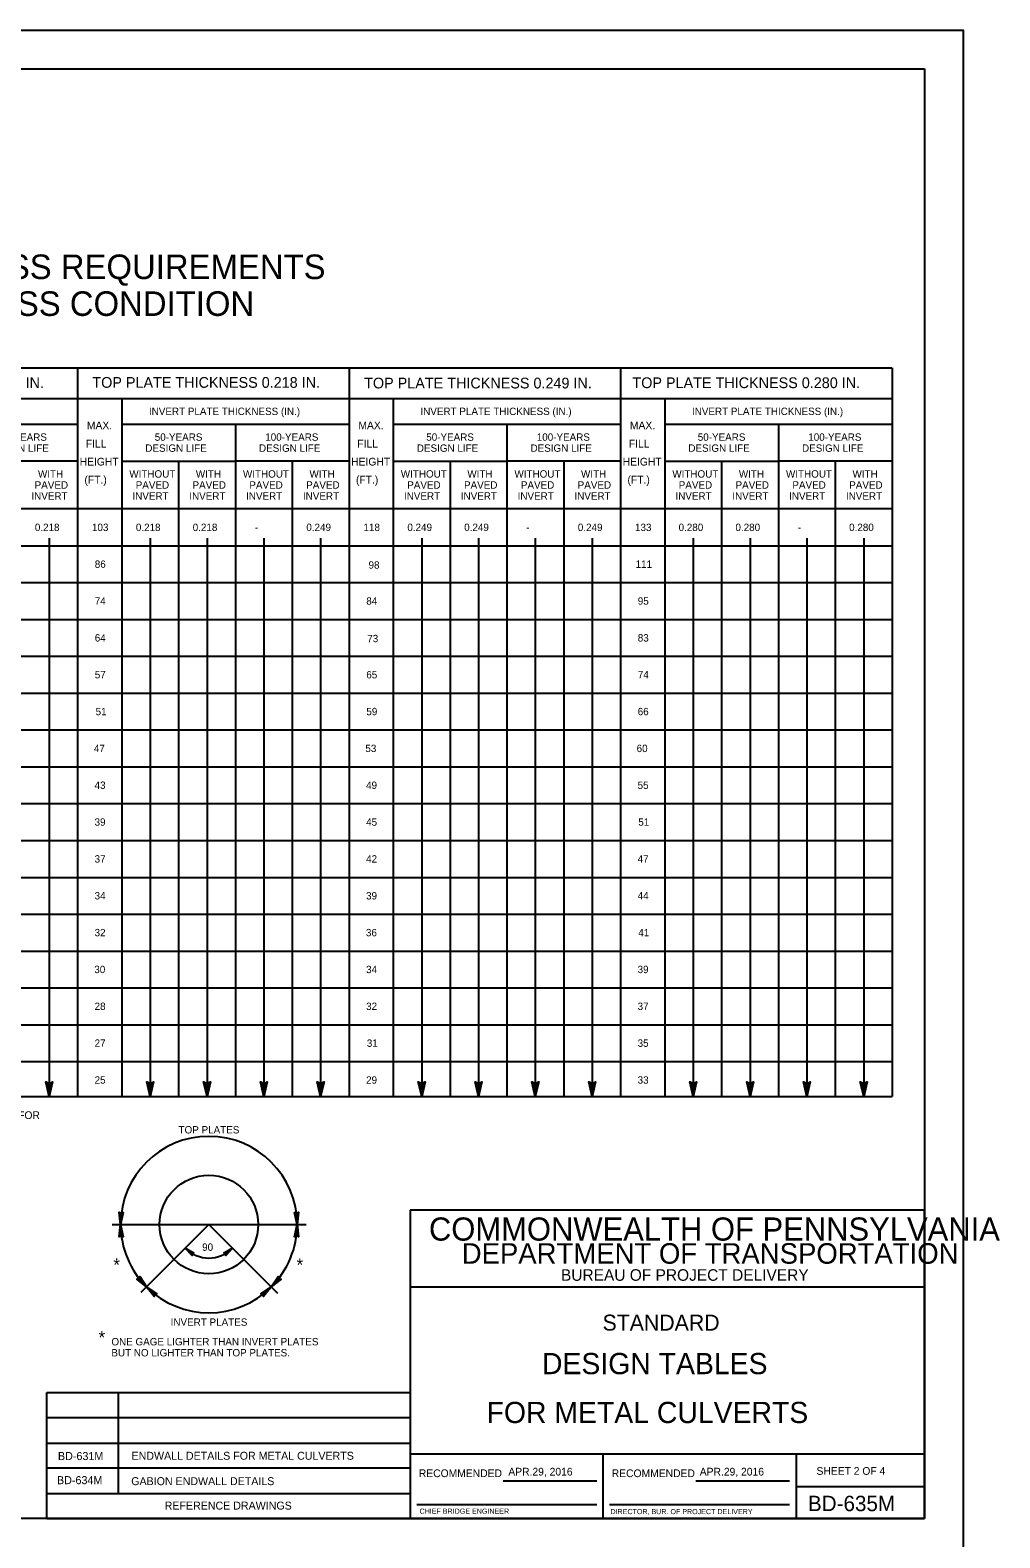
# Model space of a CAD drawing. Extents: x 591 to 2288, y -189 to 2187.
# Drawn here: x 1911 to 2288, y 1601 to 2187 of the extents above; entities that cross this region are included whole.
import ezdxf

# ---------------------------------------------------------------- set-up
doc = ezdxf.new("R2010")
doc.units = 0
for name, color, linetype in [('1', 7, 'Continuous'), ('2', 7, 'Continuous'), ('PLT-BNDY', 7, 'Continuous')]:
    doc.layers.add(name, color=color, linetype=linetype)

msp = doc.modelspace()

# ---------------------------------------------------------------- linework, layer by layer
at = {"layer": '1'}
for p, q in [((1481.73, 2055.84), (2245.62, 2055.84)), ((1928.97, 2055.84), (1928.97, 1772.38)), ((2034.53, 2055.84), (2034.53, 1772.38)), ((2140.11, 2055.84), (2140.11, 1772.38)), ((2245.68, 2055.84), (2245.68, 1772.38)), ((1823.39, 2043.97), (1928.97, 2043.97)), ((1928.97, 2043.97), (2034.53, 2043.97)), ((1946.15, 2043.97), (1946.15, 1772.38)), ((2034.53, 2043.97), (2140.11, 2043.97)), ((2051.72, 2043.97), (2051.72, 1772.38)), ((2140.11, 2043.97), (2245.68, 2043.97)), ((2157.29, 2043.97), (2157.29, 1772.38)), ((1840.58, 2033.93), (1928.97, 2033.93)), ((1946.15, 2033.93), (2034.53, 2033.93)), ((1990.34, 2033.93), (1990.34, 1772.38)), ((2051.72, 2033.93), (2140.11, 2033.93)), ((2095.91, 2033.93), (2095.91, 1772.38)), ((2157.29, 2033.93), (2245.68, 2033.93)), ((2201.48, 2033.93), (2201.48, 1772.38)), ((1928.97, 2019.6), (1884.77, 2019.6)), ((1946.15, 2019.6), (1990.34, 2019.6)), ((1968.25, 2019.6), (1968.25, 1772.38)), ((2034.53, 2019.6), (1990.34, 2019.6)), ((2012.44, 2019.6), (2012.44, 1772.38)), ((2051.72, 2019.6), (2095.91, 2019.6)), ((2073.82, 2019.6), (2073.82, 1772.38)), ((2140.11, 2019.6), (2095.91, 2019.6)), ((2118.01, 2019.6), (2118.01, 1772.38)), ((2157.29, 2019.6), (2201.48, 2019.6)), ((2179.39, 2019.6), (2179.39, 1772.38)), ((2245.68, 2019.6), (2201.48, 2019.6)), ((2223.58, 2019.6), (2223.58, 1772.38)), ((2245.68, 2000.97), (1481.73, 2000.97)), ((1917.92, 1989.55), (1917.92, 1772.38)), ((1957.2, 1989.55), (1957.2, 1772.38)), ((1979.3, 1989.55), (1979.3, 1772.38)), ((2001.39, 1989.55), (2001.39, 1772.38)), ((2023.49, 1989.55), (2023.49, 1772.38)), ((2062.77, 1989.55), (2062.77, 1772.38)), ((2084.87, 1989.55), (2084.87, 1772.38)), ((2106.96, 1989.55), (2106.96, 1772.38)), ((2129.06, 1989.55), (2129.06, 1772.38)), ((2168.34, 1989.55), (2168.34, 1772.38)), ((2190.44, 1989.55), (2190.44, 1772.38)), ((2212.53, 1989.55), (2212.53, 1772.38)), ((2234.63, 1989.55), (2234.63, 1772.38)), ((1481.73, 1986.64), (2245.68, 1986.64)), ((1481.73, 1972.31), (2245.68, 1972.31)), ((1481.73, 1957.97), (2245.68, 1957.97)), ((1481.73, 1943.64), (2245.68, 1943.64)), ((1481.73, 1929.31), (2245.68, 1929.31)), ((1481.73, 1914.98), (2245.68, 1914.98)), ((1481.73, 1900.65), (2245.68, 1900.65)), ((1481.73, 1886.31), (2245.68, 1886.31)), ((1481.73, 1871.98), (2245.68, 1871.98)), ((1481.73, 1857.65), (2245.68, 1857.65)), ((1481.73, 1843.32), (2245.68, 1843.32)), ((1481.73, 1828.99), (2245.68, 1828.99)), ((1481.73, 1814.65), (2245.68, 1814.65)), ((1481.73, 1800.32), (2245.68, 1800.32)), ((1481.73, 1785.99), (2245.68, 1785.99)), ((1481.73, 1772.38), (2245.68, 1772.38)), ((1942.48, 1722.58), (2017.89, 1722.58)), ((1980.03, 1722.58), (1953.62, 1696.17)), ((1980.03, 1722.58), (2006.67, 1695.94)), ((2133.34, 1608.21), (2133.34, 1633.21)), ((2208.34, 1633.21), (2208.34, 1608.21)), ((2094.43, 1622.93), (2130.84, 1622.93)), ((2169.43, 1622.93), (2205.84, 1622.93)), ((2060.84, 1613.71), (2130.84, 1613.71)), ((2135.84, 1613.71), (2205.84, 1613.71))]:
    msp.add_line(p, q, dxfattribs=at)
for points in [[(1918.9, 1777.8), (1918.34, 1777.59), (1917.92, 1772.38), (1918.9, 1777.8), (1919.24, 1778.08), (1917.92, 1772.38), (1917.55, 1777.59), (1916.99, 1777.78), (1917.92, 1772.38), (1916.62, 1778.08), (1916.99, 1777.78)], [(1958.18, 1777.8), (1957.61, 1777.59), (1957.2, 1772.38), (1958.18, 1777.8), (1958.52, 1778.08), (1957.2, 1772.38), (1956.83, 1777.59), (1956.26, 1777.78), (1957.2, 1772.38), (1955.89, 1778.08), (1956.26, 1777.78)], [(1980.28, 1777.8), (1979.71, 1777.59), (1979.3, 1772.38), (1980.28, 1777.8), (1980.62, 1778.08), (1979.3, 1772.38), (1978.92, 1777.59), (1978.37, 1777.78), (1979.3, 1772.38), (1977.99, 1778.08), (1978.37, 1777.78)], [(2002.37, 1777.8), (2001.81, 1777.59), (2001.39, 1772.38), (2002.37, 1777.8), (2002.71, 1778.08), (2001.39, 1772.38), (2001.02, 1777.59), (2000.46, 1777.78), (2001.39, 1772.38), (2000.09, 1778.08), (2000.46, 1777.78)], [(2024.47, 1777.8), (2023.91, 1777.59), (2023.49, 1772.38), (2024.47, 1777.8), (2024.81, 1778.08), (2023.49, 1772.38), (2023.12, 1777.59), (2022.56, 1777.78), (2023.49, 1772.38), (2022.19, 1778.08), (2022.56, 1777.78)], [(2063.75, 1777.8), (2063.18, 1777.59), (2062.77, 1772.38), (2063.75, 1777.8), (2064.09, 1778.08), (2062.77, 1772.38), (2062.4, 1777.59), (2061.84, 1777.78), (2062.77, 1772.38), (2061.46, 1778.08), (2061.84, 1777.78)], [(2085.85, 1777.8), (2085.28, 1777.59), (2084.87, 1772.38), (2085.85, 1777.8), (2086.19, 1778.08), (2084.87, 1772.38), (2084.49, 1777.59), (2083.94, 1777.78), (2084.87, 1772.38), (2083.56, 1778.08), (2083.94, 1777.78)], [(2107.94, 1777.8), (2107.38, 1777.59), (2106.96, 1772.38), (2107.94, 1777.8), (2108.28, 1778.08), (2106.96, 1772.38), (2106.59, 1777.59), (2106.03, 1777.78), (2106.96, 1772.38), (2105.66, 1778.08), (2106.03, 1777.78)], [(2130.04, 1777.8), (2129.48, 1777.59), (2129.06, 1772.38), (2130.04, 1777.8), (2130.39, 1778.08), (2129.06, 1772.38), (2128.69, 1777.59), (2128.13, 1777.78), (2129.06, 1772.38), (2127.76, 1778.08), (2128.13, 1777.78)], [(2169.32, 1777.8), (2168.75, 1777.59), (2168.34, 1772.38), (2169.32, 1777.8), (2169.66, 1778.08), (2168.34, 1772.38), (2167.97, 1777.59), (2167.41, 1777.78), (2168.34, 1772.38), (2167.03, 1778.08), (2167.41, 1777.78)], [(2191.42, 1777.8), (2190.86, 1777.59), (2190.44, 1772.38), (2191.42, 1777.8), (2191.76, 1778.08), (2190.44, 1772.38), (2190.07, 1777.59), (2189.51, 1777.78), (2190.44, 1772.38), (2189.14, 1778.08), (2189.51, 1777.78)], [(2213.51, 1777.8), (2212.95, 1777.59), (2212.53, 1772.38), (2213.51, 1777.8), (2213.86, 1778.08), (2212.53, 1772.38), (2212.16, 1777.59), (2211.6, 1777.78), (2212.53, 1772.38), (2211.23, 1778.08), (2211.6, 1777.78)], [(2235.61, 1777.8), (2235.05, 1777.59), (2234.63, 1772.38), (2235.61, 1777.8), (2235.96, 1778.08), (2234.63, 1772.38), (2234.26, 1777.59), (2233.7, 1777.78), (2234.63, 1772.38), (2233.33, 1778.08), (2233.7, 1777.78)], [(1946.51, 1727.1), (1946.18, 1726.94), (1945.7, 1722.59), (1946.51, 1727.1), (1946.72, 1727.32), (1945.7, 1722.59), (1945.72, 1726.97), (1945.4, 1727.14), (1945.7, 1722.59), (1945.2, 1727.4), (1945.4, 1727.14)], [(2014.68, 1727.16), (2014.36, 1726.97), (2014.35, 1722.59), (2014.68, 1727.16), (2014.87, 1727.4), (2014.35, 1722.59), (2013.9, 1726.94), (2013.57, 1727.08), (2014.35, 1722.59), (2013.34, 1727.32), (2013.57, 1727.08)], [(1945.37, 1718.01), (1945.69, 1718.2), (1945.7, 1722.58), (1945.37, 1718.01), (1945.18, 1717.77), (1945.7, 1722.58), (1946.15, 1718.23), (1946.48, 1718.09), (1945.7, 1722.58), (1946.71, 1717.85), (1946.48, 1718.09)], [(2013.54, 1718.07), (2013.88, 1718.22), (2014.35, 1722.58), (2013.54, 1718.07), (2013.33, 1717.85), (2014.35, 1722.58), (2014.34, 1718.2), (2014.65, 1718.03), (2014.35, 1722.58), (2014.86, 1717.77), (2014.65, 1718.03)], [(1973.44, 1710.84), (1973.48, 1711.13), (1970.82, 1713.37), (1973.44, 1710.84), (1973.49, 1710.59), (1970.82, 1713.37), (1973.71, 1711.42), (1973.96, 1711.55), (1970.82, 1713.37), (1974.22, 1711.57), (1973.96, 1711.55)], [(1986.07, 1711.56), (1986.34, 1711.43), (1989.23, 1713.37), (1986.07, 1711.56), (1985.82, 1711.57), (1989.23, 1713.37), (1986.56, 1711.14), (1986.62, 1710.86), (1989.23, 1713.37), (1986.56, 1710.6), (1986.62, 1710.86)], [(1953.14, 1702.07), (1953.01, 1701.72), (1955.76, 1698.31), (1953.14, 1702.07), (1953.13, 1702.37), (1955.76, 1698.31), (1952.67, 1701.41), (1952.32, 1701.31), (1955.76, 1698.31), (1952, 1701.35), (1952.32, 1701.31)], [(2007.76, 1701.3), (2007.4, 1701.4), (2004.3, 1698.31), (2007.76, 1701.3), (2008.07, 1701.34), (2004.3, 1698.31), (2007.06, 1701.7), (2006.93, 1702.04), (2004.3, 1698.31), (2006.93, 1702.37), (2006.93, 1702.04)], [(1958.75, 1694.84), (1958.85, 1695.2), (1955.76, 1698.31), (1958.75, 1694.84), (1958.79, 1694.54), (1955.76, 1698.31), (1959.15, 1695.54), (1959.49, 1695.68), (1955.76, 1698.31), (1959.82, 1695.67), (1959.49, 1695.68)], [(2000.54, 1695.69), (2000.89, 1695.56), (2004.3, 1698.31), (2000.54, 1695.69), (2000.23, 1695.69), (2004.3, 1698.31), (2001.19, 1695.23), (2001.29, 1694.87), (2004.3, 1698.31), (2001.25, 1694.55), (2001.29, 1694.87)]]:
    msp.add_lwpolyline(points, dxfattribs=at)
msp.add_circle((1980.03, 1722.58), 19.18, dxfattribs=at)
for radius, start, end in [(34.32, 0.01323, 179.98674), (34.32, 180, 225.00216), (34.32, 315, 0), (13.02, 225.00216, 315), (34.32, 225.00216, 315)]:
    msp.add_arc((1980.03, 1722.58), radius, start, end, dxfattribs=at)
at = {"layer": '2'}
for p, q in [((1472.34, 2172.21), (2258.34, 2172.21)), ((2258.34, 2172.21), (2258.34, 1608.21)), ((2258.34, 1728.21), (2058.34, 1728.21)), ((2058.34, 1728.21), (2058.34, 1608.21)), ((2258.34, 1608.21), (2258.34, 1728.21)), ((2258.34, 1698.21), (2058.34, 1698.21)), ((1916.96, 1608.21), (1916.96, 1657.21)), ((1916.96, 1657.21), (2058.34, 1657.21)), ((1916.96, 1657.21), (2058.34, 1657.21)), ((1944.84, 1618.34), (1944.84, 1657.21)), ((1916.96, 1647.59), (2058.34, 1647.59)), ((1916.96, 1637.59), (2058.34, 1637.59)), ((2258.34, 1633.21), (2058.34, 1633.21)), ((1916.96, 1627.96), (2058.34, 1627.96)), ((2208.34, 1620.71), (2258.34, 1620.71)), ((1916.96, 1617.96), (2058.34, 1617.96)), ((2258.34, 1608.21), (1472.34, 1608.21)), ((2258.34, 1608.21), (1472.34, 1608.21)), ((1916.96, 1608.21), (2058.34, 1608.21)), ((2058.34, 1608.21), (2258.34, 1608.21)), ((2058.34, 1608.21), (2258.34, 1608.21))]:
    msp.add_line(p, q, dxfattribs=at)
at = {"layer": 'PLT-BNDY'}
msp.add_lwpolyline([(1432.34, 2187.21), (2273.34, 2187.21), (2273.34, 1593.21), (1432.34, 1593.21)], close=True, dxfattribs=at)

# ---------------------------------------------------------------- texts
at = {"layer": '1'}
for s, height, p in [('STEEL STRUCTURAL PLATE PIPE THICKNESS REQUIREMENTS', 9.5546, (1635.62, 2090.38)), ('WITH MINIMUM  PREDICTED METAL LOSS CONDITION', 9.5546, (1664.02, 2076.05)), ('TOP PLATE THICKNESS 0.188 IN.', 4.1801, (1827.37, 2047.96)), ('TOP PLATE THICKNESS 0.218 IN.', 4.1801, (1934.72, 2048.08)), ('TOP PLATE THICKNESS 0.249 IN.', 4.1801, (2040.39, 2047.84)), ('TOP PLATE THICKNESS 0.280 IN.', 4.1801, (2144.72, 2047.96)), ('INVERT PLATE THICKNESS (IN.)', 2.8664, (1956.72, 2037.49)), ('INVERT PLATE THICKNESS (IN.)', 2.8664, (2062.29, 2037.49)), ('INVERT PLATE THICKNESS (IN.)', 2.8664, (2167.86, 2037.49)), ('100-YEARS', 2.866, (1896.38, 2027.48)), ('50-YEARS', 2.866, (1958.98, 2027.48)), ('100-YEARS', 2.866, (2001.95, 2027.48)), ('50-YEARS', 2.866, (2064.55, 2027.48)), ('100-YEARS', 2.866, (2107.52, 2027.48)), ('50-YEARS', 2.866, (2170.12, 2027.48)), ('100-YEARS', 2.866, (2213.09, 2027.48)), ('DESIGN LIFE', 2.8664, (1893.94, 2023.19)), ('DESIGN LIFE', 2.8664, (1955.32, 2023.19)), ('DESIGN LIFE', 2.8664, (1999.52, 2023.19)), ('DESIGN LIFE', 2.8664, (2060.89, 2023.19)), ('DESIGN LIFE', 2.8664, (2105.09, 2023.19)), ('DESIGN LIFE', 2.8664, (2166.46, 2023.19)), ('DESIGN LIFE', 2.8664, (2210.66, 2023.19)), ('PAVED', 2.866, (1912.29, 2008.85)), ('WITH', 2.866, (1913.58, 2013.15)), ('WITHOUT', 2.866, (1949.09, 2013.15)), ('PAVED', 2.866, (1951.58, 2008.85)), ('PAVED', 2.866, (1973.67, 2008.85)), ('WITH', 2.866, (1974.96, 2013.15)), ('WITHOUT', 2.866, (1993.28, 2013.15)), ('PAVED', 2.866, (1995.77, 2008.85)), ('PAVED', 2.866, (2017.87, 2008.85)), ('WITH', 2.866, (2019.15, 2013.15)), ('WITHOUT', 2.866, (2054.66, 2013.15)), ('PAVED', 2.866, (2057.15, 2008.85)), ('PAVED', 2.866, (2079.24, 2008.85)), ('WITH', 2.866, (2080.53, 2013.15)), ('WITHOUT', 2.866, (2098.85, 2013.15)), ('PAVED', 2.866, (2101.34, 2008.85)), ('PAVED', 2.866, (2123.43, 2008.85)), ('WITH', 2.866, (2124.72, 2013.15)), ('WITHOUT', 2.866, (2160.23, 2013.15)), ('PAVED', 2.866, (2162.72, 2008.85)), ('PAVED', 2.866, (2184.81, 2008.85)), ('WITH', 2.866, (2186.1, 2013.15)), ('WITHOUT', 2.866, (2204.42, 2013.15)), ('PAVED', 2.866, (2206.91, 2008.85)), ('PAVED', 2.866, (2229, 2008.85)), ('WITH', 2.866, (2230.29, 2013.15)), ('INVERT', 2.866, (1911.03, 2004.56)), ('INVERT', 2.866, (1950.31, 2004.56)), ('INVERT', 2.866, (1972.41, 2004.56)), ('INVERT', 2.866, (1994.5, 2004.56)), ('INVERT', 2.866, (2016.6, 2004.56)), ('INVERT', 2.866, (2055.88, 2004.56)), ('INVERT', 2.866, (2077.98, 2004.56)), ('INVERT', 2.866, (2100.07, 2004.56)), ('INVERT', 2.866, (2122.17, 2004.56)), ('INVERT', 2.866, (2161.45, 2004.56)), ('INVERT', 2.866, (2183.55, 2004.56)), ('INVERT', 2.866, (2205.64, 2004.56)), ('INVERT', 2.866, (2227.74, 2004.56)), ('0.218', 2.866, (1912.36, 1992.37)), ('103', 2.866, (1934.57, 1992.37)), ('0.218', 2.866, (1951.64, 1992.37)), ('0.218', 2.866, (1973.74, 1992.37)), ('0.249', 2.866, (2017.92, 1992.37)), ('118', 2.866, (2040.14, 1992.37)), ('0.249', 2.866, (2057.2, 1992.37)), ('0.249', 2.866, (2079.3, 1992.37)), ('0.249', 2.866, (2123.49, 1992.37)), ('133', 2.866, (2145.72, 1992.37)), ('0.280', 2.866, (2162.67, 1992.37)), ('0.280', 2.866, (2184.78, 1992.37)), ('0.280', 2.866, (2228.97, 1992.37)), ('-', 2.87, (1997.86, 1992.37)), ('-', 2.87, (2103.43, 1992.37)), ('-', 2.87, (2209, 1992.37)), ('86', 2.866, (1935.66, 1978.04)), ('98', 2.866, (2042.1, 1977.72)), ('111', 2.866, (2145.93, 1978.04)), ('74', 2.866, (1935.66, 1963.71)), ('84', 2.866, (2041.23, 1963.71)), ('95', 2.866, (2146.8, 1963.71)), ('64', 2.866, (1935.66, 1949.38)), ('73', 2.866, (2041.61, 1949.12)), ('83', 2.866, (2146.8, 1949.38)), ('57', 2.866, (1935.67, 1935.04)), ('65', 2.866, (2041.24, 1935.04)), ('74', 2.866, (2146.81, 1935.04)), ('51', 2.866, (1935.98, 1920.71)), ('59', 2.866, (2041.26, 1920.71)), ('66', 2.866, (2146.77, 1920.71)), ('47', 2.866, (1935.31, 1906.38)), ('53', 2.866, (2040.88, 1906.38)), ('60', 2.866, (2146.35, 1906.38)), ('43', 2.866, (1935.59, 1892.05)), ('49', 2.866, (2041.15, 1892.05)), ('55', 2.866, (2146.73, 1892.05)), ('39', 2.866, (1935.58, 1877.72)), ('45', 2.866, (2041.16, 1877.72)), ('51', 2.866, (2147.01, 1877.72)), ('37', 2.866, (1935.59, 1863.38)), ('42', 2.866, (2041.16, 1863.38)), ('47', 2.866, (2146.73, 1863.38)), ('34', 2.866, (1935.59, 1849.05)), ('39', 2.866, (2041.15, 1849.05)), ('44', 2.866, (2146.73, 1849.05)), ('32', 2.866, (1935.59, 1834.72)), ('36', 2.866, (2041.09, 1834.72)), ('41', 2.866, (2147.01, 1834.72)), ('30', 2.866, (1935.48, 1820.39)), ('34', 2.866, (2041.16, 1820.39)), ('39', 2.866, (2146.72, 1820.39)), ('28', 2.866, (1935.59, 1806.06)), ('32', 2.866, (2041.16, 1806.06)), ('37', 2.866, (2146.73, 1806.06)), ('27', 2.866, (1935.59, 1791.72)), ('31', 2.866, (2041.44, 1791.72)), ('35', 2.866, (2146.73, 1791.72)), ('25', 2.866, (1935.59, 1777.39)), ('29', 2.866, (2041.15, 1777.39)), ('33', 2.866, (2146.73, 1777.39)), ('TOP PLATES', 2.866, (1968.24, 1758.02)), ('90', 2.866, (1977.41, 1712.36)), ('*', 4.95, (1942.88, 1704.44)), ('*', 4.95, (2014.13, 1704.44)), ('INVERT PLATES', 2.8664, (1965.16, 1683.21)), ('*', 4.95, (1937.12, 1676.19)), ('ONE GAGE LIGHTER THAN INVERT PLATES', 2.8664, (1942.12, 1675.58)), ('BUT NO LIGHTER THAN TOP PLATES.', 2.8664, (1942.12, 1671.29)), ('RECOMMENDED', 3, (2061.67, 1624.34)), ('RECOMMENDED', 3, (2136.67, 1624.34)), ('CHIEF BRIDGE ENGINEER', 2.0003, (2061.93, 1610.09)), ('DIRECTOR, BUR. OF PROJECT DELIVERY', 2.0003, (2136.17, 1609.93))]:
    msp.add_text(s, height=height, dxfattribs=at).set_placement(p)
at = {"layer": '2'}
for s, height, p in [('MAX.', 3, (1932.59, 2031.97)), ('MAX.', 3, (2038.16, 2031.97)), ('MAX.', 3, (2143.73, 2031.97)), ('FILL', 3, (1932.17, 2024.85)), ('FILL', 3, (2037.74, 2024.85)), ('FILL', 3, (2143.32, 2024.85)), ('HEIGHT', 3, (1929.78, 2017.85)), ('HEIGHT', 3, (2035.35, 2017.85)), ('HEIGHT', 3, (2140.92, 2017.85)), ('(FT.)', 3, (1931.64, 2010.85)), ('(FT.)', 3, (2037.21, 2010.85)), ('(FT.)', 3, (2142.79, 2010.85)), ('REFER TO DM4, FIGURE 12.6.9.5P-2 FOR', 3, (1835.64, 1763.63)), ('COMMONWEALTH OF PENNSYLVANIA', 9, (2065.59, 1716.34)), ('DEPARTMENT OF TRANSPORTATION', 8.0002, (2078.34, 1707.34)), ('BUREAU OF PROJECT DELIVERY', 4.5, (2116.93, 1700.71)), ('STANDARD', 6.188, (2133.09, 1681.34)), ('DESIGN TABLES', 8.2515, (2109.55, 1664.38)), ('FOR METAL CULVERTS', 8.2515, (2088.01, 1645.36)), ('BD-631M', 3.125, (1921.34, 1630.96)), ('ENDWALL DETAILS FOR METAL CULVERTS', 3.0938, (1949.96, 1631.09)), ('BD-634M', 3.125, (1920.96, 1621.59)), ('APR.29, 2016', 3, (2096.47, 1624.95)), ('APR.29, 2016', 3, (2170.89, 1624.95)), ('SHEET 2 OF 4', 3, (2216.28, 1625.23)), ('GABION ENDWALL DETAILS', 3.0938, (1949.84, 1621.21)), ('REFERENCE DRAWINGS', 3.093, (1962.84, 1611.71)), ('BD-635M', 6, (2212.96, 1611.09))]:
    msp.add_text(s, height=height, dxfattribs=at).set_placement(p)

doc.saveas('drawing.dxf')
